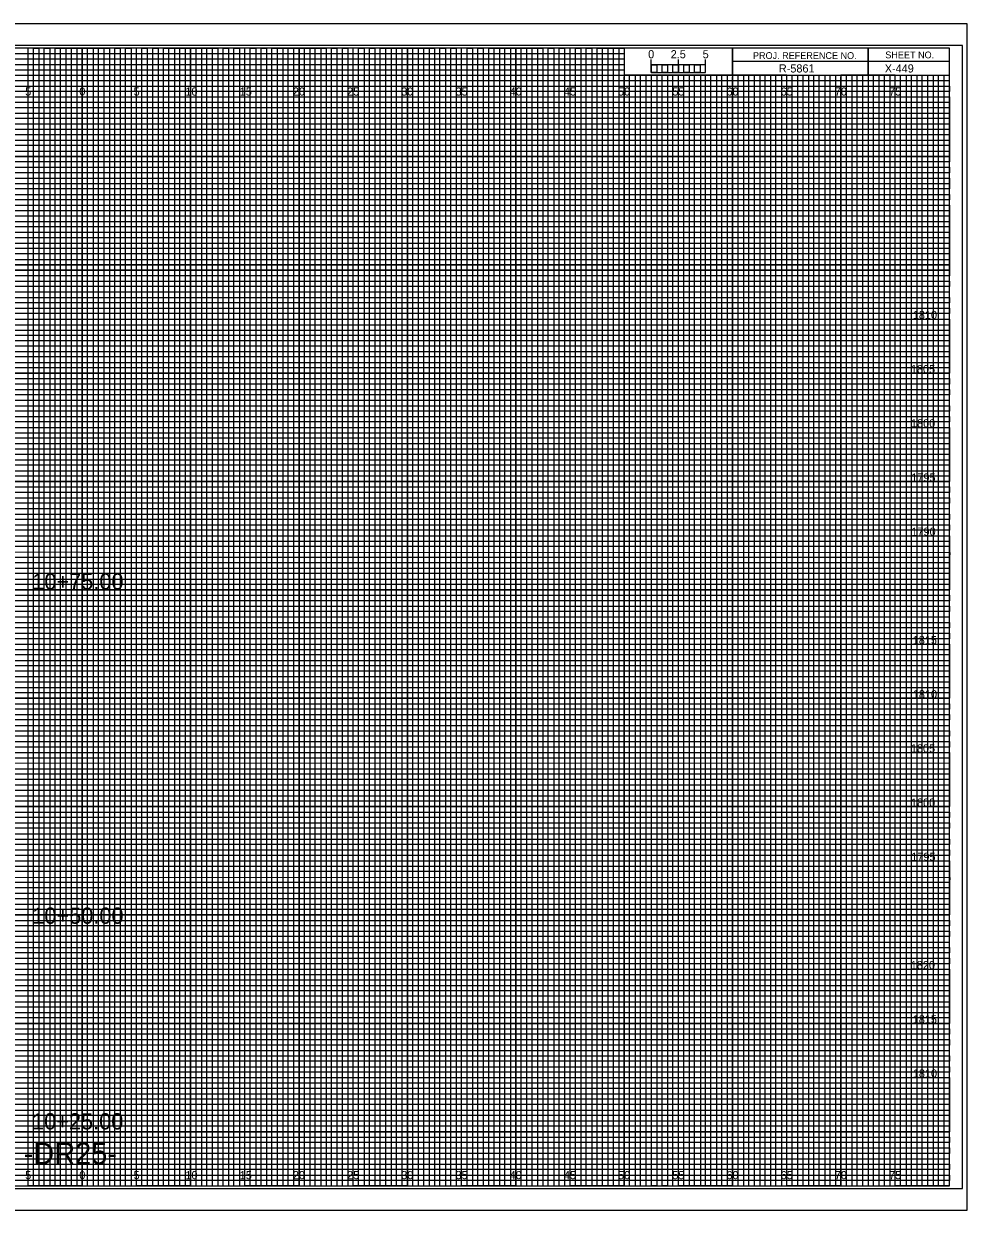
# Model space of a CAD drawing. Extents: x -7 to 162, y -2 to 327.
# Drawn here: x 74.6 to 161.7, y -2.3 to 107.3 of the extents above; entities that cross this region are included whole.
import ezdxf

# ---------------------------------------------------------------- set-up
doc = ezdxf.new("R2010")
doc.units = 0
for name, color, linetype in [('Prop Horizontal Alignment', 7, 'Continuous'), ('Prop XS Alignment Label', 7, 'Continuous'), ('Prop XS Bar Scale Labels', 7, 'Continuous'), ('Prop XS Project Number', 7, 'Continuous'), ('Prop XS Sheet Number', 7, 'Continuous'), ('Raster_Level_0', 7, 'Continuous'), ('Scratch_Level_3', 7, 'Continuous'), ('Sheet Cross Section CELL', 7, 'Continuous'), ('Sheet Cross Section Grid Major CELL', 7, 'Continuous'), ('Sheet Cross Section Grid Middle CELL', 7, 'Continuous'), ('Sheet Cross Section Grid Minor 1 CELL', 7, 'Continuous'), ('Sheet Cross Section Grid Minor 2 CELL', 7, 'Continuous'), ('Sheet Cross Section Scale CELL', 7, 'Continuous'), ('Sheet Cutting Line CELL', 7, 'Continuous'), ('Sheet DOT Grid CELL', 7, 'Continuous'), ('Sheet Plot Border Inside CELL', 7, 'Continuous'), ('Sheet Plot Border Outside CELL', 7, 'Continuous')]:
    doc.layers.add(name, color=color, linetype=linetype)

msp = doc.modelspace()

# ---------------------------------------------------------------- linework, layer by layer
at = {"layer": 'Sheet Cross Section CELL'}
for p, q in [((152.5, 105), (152.5, 102.5)), ((152.5, 102.5), (152.5, 105)), ((160, 103.75), (140, 103.75)), ((140, 103.75), (140, 102.5)), ((140, 102.5), (160, 102.5))]:
    msp.add_line(p, q, dxfattribs=at)
for points in [[(160, 105), (0, 105), (0, 0), (160, 0)], [(140, 105), (130, 105), (130, 102.52), (140, 102.52)], [(160, 105), (140, 105), (140, 102.5), (160, 102.5)]]:
    msp.add_lwpolyline(points, close=True, dxfattribs=at)
at = {"layer": 'Sheet Cross Section Grid Major CELL'}
for p, q in [((75, 105), (70, 105)), ((75, 0), (75, 105)), ((85, 105), (80, 105)), ((80, 105), (80, 0)), ((85, 0), (85, 105)), ((95, 105), (90, 105)), ((90, 105), (90, 0)), ((95, 0), (95, 105)), ((105, 105), (100, 105)), ((100, 105), (100, 0)), ((105, 0), (105, 105)), ((115, 105), (110, 105)), ((110, 105), (110, 0)), ((115, 0), (115, 105)), ((125, 105), (120, 105)), ((120, 105), (120, 0)), ((125, 0), (125, 105)), ((130, 105), (130, 0)), ((135, 0), (135, 102.5)), ((145, 102.5), (140, 102.5)), ((140, 102.5), (140, 0)), ((145, 0), (145, 102.5)), ((155, 102.5), (150, 102.5)), ((150, 102.5), (150, 0)), ((155, 0), (155, 102.5)), ((80, 0), (75, 0)), ((90, 0), (85, 0)), ((100, 0), (95, 0)), ((110, 0), (105, 0)), ((120, 0), (115, 0)), ((130, 0), (125, 0)), ((140, 0), (135, 0)), ((150, 0), (145, 0)), ((160, 0), (155, 0)), ((160, 0), (160, 0))]:
    msp.add_line(p, q, dxfattribs=at)
for points in [[(0, 100), (160, 100), (160, 95), (0, 95)], [(0, 90), (160, 90), (160, 85), (0, 85)], [(0, 80), (160, 80), (160, 75), (0, 75)], [(0, 70), (160, 70), (160, 65), (0, 65)], [(0, 60), (160, 60), (160, 55), (0, 55)], [(0, 50), (160, 50), (160, 45), (0, 45)], [(0, 40), (160, 40), (160, 35), (0, 35)], [(0, 30), (160, 30), (160, 25), (0, 25)], [(0, 20), (160, 20), (160, 15), (0, 15)], [(0, 10), (160, 10), (160, 5), (0, 5)]]:
    msp.add_lwpolyline(points, dxfattribs=at)
at = {"layer": 'Sheet Cross Section Grid Middle CELL'}
for points in [[(72.5, 0), (77.5, 0), (77.5, 105), (82.5, 105), (82.5, 0), (87.5, 0), (87.5, 105), (92.5, 105), (92.5, 0), (97.5, 0), (97.5, 105), (102.5, 105), (102.5, 0), (107.5, 0), (107.5, 105), (112.5, 105), (112.5, 0), (117.5, 0), (117.5, 105), (122.5, 105), (122.5, 0), (127.5, 0), (127.5, 105), (129.97, 105), (130, 105), (130, 102.5), (132.5, 102.5), (132.5, 0), (137.5, 0), (137.5, 102.5), (142.5, 102.5), (142.5, 0), (147.5, 0), (147.5, 102.5), (152.5, 102.5), (152.5, 0), (157.5, 0), (157.5, 102.5)], [(0, 102.5), (137.5, 102.5)], [(0, 92.5), (160, 92.5), (160, 97.5), (0, 97.5)], [(0, 82.5), (160, 82.5), (160, 87.5), (0, 87.5)], [(0, 72.5), (160, 72.5), (160, 77.5), (0, 77.5)], [(0, 62.5), (160, 62.5), (160, 67.5), (0, 67.5)], [(0, 52.5), (160, 52.5), (160, 57.5), (0, 57.5)], [(0, 42.5), (160, 42.5), (160, 47.5), (0, 47.5)], [(0, 32.5), (160, 32.5), (160, 37.5), (0, 37.5)], [(0, 22.5), (160, 22.5), (160, 27.5), (0, 27.5)], [(0, 12.5), (160, 12.5), (160, 17.5), (0, 17.5)], [(0, 2.5), (160, 2.5), (160, 7.5), (0, 7.5)]]:
    msp.add_lwpolyline(points, dxfattribs=at)
at = {"layer": 'Sheet Cross Section Grid Minor 1 CELL'}
for p, q in [((0, 104.5), (130, 104.5)), ((130, 104.5), (130, 103.99)), ((130, 103.99), (0, 103.99)), ((0, 103.5), (130, 103.5)), ((130, 102.95), (0, 102.95)), ((130, 103.5), (130, 102.95)), ((0, 102), (160, 102))]:
    msp.add_line(p, q, dxfattribs=at)
for points in [[(0, 101.5), (135, 101.5), (160, 101.5), (160, 101), (0, 101)], [(0, 100.5), (160, 100.5), (160, 99.5), (0, 99.5)], [(0, 99), (160, 99), (160, 98.5), (0, 98.49)], [(0, 98), (160, 98), (160, 97), (0, 97)], [(0, 96.5), (160, 96.5), (160, 96), (0, 96)], [(0, 95.5), (160, 95.5), (160, 94.5), (0, 94.5)], [(0, 94), (160, 94), (160, 93.5), (0, 93.5)], [(0, 93), (160, 93), (160, 92), (0, 92)], [(0, 91.5), (160, 91.5), (160, 91), (0, 91)], [(0, 90.5), (160, 90.5), (160, 89.5), (0, 89.5)], [(0, 89), (160, 89), (160, 88.5), (0, 88.5)], [(0, 88), (160, 88), (160, 86.98), (160, 86.5), (160, 86), (0, 86)], [(0, 87), (160, 87), (160, 86.5), (0, 86.5)], [(0, 85.5), (160, 85.5), (160, 84.5), (0, 84.52)], [(0, 84.52), (160, 84.5), (160, 84), (0, 84)], [(0, 83.5), (160, 83.5), (160, 83), (0, 83)], [(0, 82), (160, 82), (160, 81.5), (0, 81.5)], [(0, 81), (160, 81), (160, 80.5), (0, 80.5)], [(-0.04, 79.45), (160, 79.45), (160, 78.94), (-0.04, 78.94)], [(0, 78.5), (160, 78.5), (160, 78), (0, 78)], [(0, 77), (160, 77), (160, 76.5), (0, 76.5)], [(0, 76), (160, 76), (160, 75.5), (0, 75.5)], [(0, 74.5), (160, 74.5), (160, 74), (0, 74)], [(0, 73.5), (160, 73.5), (160, 73), (0, 73)], [(0, 72), (160, 72), (160, 71.5), (0, 71.5)], [(0, 71), (160, 71), (160, 70.5), (0, 70.5)], [(0, 69.5), (160, 69.5), (160, 68.99), (0, 69)], [(0, 68.5), (160, 68.5), (160, 68), (0, 68)], [(0, 67), (160, 67), (160, 66.5), (0, 66.5)], [(0, 66), (160, 66), (160, 65.5), (0, 65.5)], [(0, 64.5), (160, 64.5), (160, 64), (0, 64)], [(0, 63.5), (160, 63.5), (160, 63), (0, 63)], [(0, 62), (160, 62), (160, 61.5), (0, 61.5)], [(0, 61), (160, 61), (160, 60.5), (0, 60.5)], [(0, 59.5), (160, 59.5), (160, 59), (0, 59)], [(0, 58.5), (160.03, 58.45), (160, 58), (0, 58)], [(0, 57), (160, 57), (160, 56.5), (0, 56.5)], [(0, 56), (160, 56), (160, 55.5), (0, 55.5)], [(0, 54.5), (160, 54.5), (160, 54), (0, 54)], [(0, 53.5), (160, 53.5), (160, 53), (0, 53)], [(0, 52), (160, 52), (160, 51.5), (0, 51.5)], [(0, 51), (160, 51), (160, 50.5), (0, 50.5)], [(0, 49.5), (160, 49.5), (160, 49), (0, 49)], [(0, 48.5), (160, 48.5), (160, 48), (0, 48)], [(0, 47), (160, 47), (160, 46.5), (0, 46.5)], [(0, 46), (160, 46), (160, 45.5), (0, 45.5)], [(0, 44.5), (160, 44.5), (160, 44), (0, 44)], [(0, 43.5), (160, 43.5), (160, 43), (0, 43)], [(0, 42), (160, 42), (160, 41.5), (0, 41.5)], [(0, 41), (160, 41), (160, 40.5), (0, 40.5)], [(0, 39.5), (160, 39.5), (160, 38.99), (0, 39)], [(0, 38.5), (160, 38.5), (160, 38), (0, 38)], [(0, 37), (160, 37), (160, 36.5), (0, 36.5)], [(0, 36), (160, 36), (160, 35.5), (0, 35.5)], [(0, 34.5), (160, 34.5), (160, 34), (0, 34)], [(0, 33.5), (160, 33.5), (160, 33), (0, 33)], [(0, 32), (160, 32), (160, 31.5), (0, 31.5)], [(0, 31), (160, 31), (160, 30.5), (0, 30.5)], [(0, 29.5), (160, 29.5), (160, 29), (0, 29)], [(0, 28.5), (160.03, 28.46), (160, 28), (0, 28)], [(0, 27), (160, 27), (160, 26.5), (0, 26.5)], [(0, 26), (160, 26), (160, 25.5), (0, 25.5)], [(0, 24.5), (160, 24.5), (160, 24), (0, 24)], [(0, 23.5), (160, 23.5), (160, 23), (0, 23)], [(0, 22), (160, 22), (160, 21.5), (0, 21.5)], [(0, 21), (160, 21), (160, 20.5), (0, 20.5)], [(0, 19.5), (160, 19.5), (160, 19), (0, 19)], [(0, 18.5), (160, 18.5), (160, 18), (0, 18)], [(0, 17), (160, 17), (160, 16.5), (0, 16.5)], [(0, 16), (160, 16), (160, 15.5), (0, 15.5)], [(0, 14.5), (160, 14.5), (160, 14), (0, 14)], [(0, 13.5), (160, 13.5), (160, 13), (0, 13)], [(0, 12), (160, 12), (160, 11.5), (0, 11.5)], [(0, 11), (160, 11), (160, 10.5), (0, 10.5)], [(0, 9.5), (160, 9.5), (160, 9), (0, 9)], [(0, 8.5), (160, 8.5), (160, 8), (0, 8)], [(0, 7), (160, 7), (160, 6.5), (0, 6.5)], [(0, 6), (160, 6), (160, 5.5), (0, 5.5)], [(0, 4.5), (160, 4.5), (160, 4), (0, 4)], [(0, 3.5), (160, 3.5), (160, 3), (0, 3)], [(0, 2), (160, 2), (160, 1.5), (0, 1.5)], [(0, 1), (160, 1), (160, 0.5), (0, 0.5)]]:
    msp.add_lwpolyline(points, dxfattribs=at)
at = {"layer": 'Sheet Cross Section Grid Minor 2 CELL'}
for p, q in [((133.5, 102.5), (133, 102.5)), ((133, 102.5), (133, 0)), ((133.5, 0), (133.5, 102.5)), ((134.5, 102.5), (134, 102.5)), ((134, 102.5), (134, 0)), ((134.5, 0), (134.5, 102.5)), ((133, 0), (132.5, 0)), ((134, 0), (133.5, 0))]:
    msp.add_line(p, q, dxfattribs=at)
for points in [[(75, 0), (75.5, 0), (75.5, 105), (76, 105), (76, 0)], [(76, 0), (76.5, 0), (76.5, 105), (77, 105), (77, 0)], [(77.5, 0), (78, 0), (78, 105), (78.5, 105), (78.5, 0)], [(78.5, 0), (79, 0), (79, 105), (79.5, 105), (79.5, 0)], [(80, 0), (80.5, 0), (80.5, 105), (81, 105), (81, 0)], [(81, 0), (81.5, 0), (81.5, 105), (82, 105), (82, 0)], [(82.5, 0), (83, 0), (83, 105), (83.5, 105), (83.5, 0)], [(83.5, 0), (84, 0), (84, 105), (84.5, 105), (84.5, 0)], [(85, 0), (85.5, 0), (85.5, 105), (86, 105), (86, 0)], [(86, 0), (86.5, 0), (86.5, 105), (87, 105), (87, 0)], [(87.5, 0), (88, 0), (88, 105), (88.5, 105), (88.5, 0)], [(88.5, 0), (89, 0), (89, 105), (89.5, 105), (89.5, 0)], [(90, 0), (90.5, 0), (90.5, 105), (91, 105), (91, 0)], [(91, 0), (91.5, 0), (91.5, 105), (92, 105), (92, 0)], [(92.5, 0), (93, 0), (93, 105), (93.5, 105), (93.5, 0)], [(93.5, 0), (94, 0), (94, 105), (94.5, 105), (94.5, 0)], [(95, 0), (95.5, 0), (95.5, 105), (96, 105), (96, 0)], [(96, 0), (96.5, 0), (96.5, 105), (97, 105), (97, 0)], [(97.5, 0), (98, 0), (98, 105), (98.5, 105), (98.5, 0)], [(98.5, 0), (99, 0), (99, 105), (99.5, 105), (99.5, 0)], [(100, 0), (100.5, 0), (100.5, 105), (101, 105), (101, 0)], [(101, 0), (101.5, 0), (101.5, 105), (102, 105), (102, 0)], [(102.5, 0), (103, 0), (103, 105), (103.5, 105), (103.5, 0)], [(103.5, 0), (104, 0), (104, 105), (104.5, 105), (104.5, 0)], [(105, 0), (105.5, 0), (105.5, 105), (106, 105), (106, 0)], [(106, 0), (106.5, 0), (106.5, 105), (107, 105), (107, 0)], [(107.5, 0), (108, 0), (108, 105), (108.5, 105), (108.5, 0)], [(108.5, 0), (109, 0), (109, 105), (109.5, 105), (109.5, 0)], [(110, 0), (110.5, 0), (110.5, 105), (111, 105), (111, 0)], [(111, 0), (111.5, 0), (111.5, 105), (112, 105), (112, 0)], [(112.5, 0), (113, 0), (113, 105), (113.5, 105), (113.5, 0)], [(113.5, 0), (114, 0), (114, 105), (114.5, 105), (114.5, 0)], [(115, 0), (115.5, 0), (115.5, 105), (116, 105), (116, 0)], [(116, 0), (116.5, 0), (116.5, 105), (117, 105), (117, 0)], [(117.5, 0), (118, 0), (118, 105), (118.5, 105), (118.5, 0)], [(118.5, 0), (119, 0), (119, 105), (119.5, 105), (119.5, 0)], [(120, 0), (120.5, 0), (120.5, 105), (121, 105), (121, 0)], [(121, 0), (121.5, 0), (121.5, 105), (122, 105), (122, 0)], [(122.5, 0), (123, 0), (123, 105), (123.5, 105), (123.5, 0)], [(123.5, 0), (124, 0), (124, 105), (124.5, 105), (124.5, 0)], [(125, 0), (125.5, 0), (125.5, 105), (126, 105), (126, 0)], [(126, 0), (126.5, 0), (126.5, 105), (127, 105), (127, 0)], [(127.5, 0), (128, 0), (128, 105), (128.5, 105), (128.5, 0)], [(128.5, 0), (129, 0), (129, 105), (129.5, 105), (129.5, 0)], [(130, 0), (130.5, 0), (130.5, 102.5), (131.01, 102.5), (131.01, 0)], [(131, 0), (131.5, 0), (131.5, 102.5), (132, 102.5), (132, 0)], [(135, 0), (135.49, 0), (135.49, 102.5), (136, 102.5), (136, 0)], [(136, 0), (136.5, 0), (136.5, 102.5), (137.03, 102.5), (137.03, 0)], [(137.5, 0), (138, 0), (138, 102.5), (138.5, 102.5), (138.5, 0)], [(138.5, 0), (139, 0), (139, 102.5), (139.5, 102.5), (139.5, 0)], [(140, 0), (140.5, 0), (140.5, 102.5), (141, 102.5), (141, 0)], [(141, 0), (141.5, 0), (141.5, 102.5), (142, 102.5), (142, 0)], [(142.5, 0), (143, 0), (143, 102.5), (143.5, 102.5), (143.5, 0)], [(143.5, 0), (144, 0), (144, 102.5), (144.5, 102.5), (144.5, 0)], [(145, 0), (145.5, 0), (145.5, 102.5), (146, 102.5), (146, 0)], [(146, 0), (146.5, 0), (146.5, 102.5), (147, 102.5), (147, 0)], [(147.5, 0), (148, 0), (148, 102.5), (148.5, 102.5), (148.5, 0)], [(148.5, 0), (149, 0), (149, 102.5), (149.5, 102.5), (149.5, 0)], [(150, 0), (150.5, 0), (150.5, 102.5), (151, 102.5), (151, 0)], [(151, 0), (151.5, 0), (151.5, 102.5), (152, 102.5), (152, 0)], [(152.5, 0), (153, 0), (153, 102.5), (153.5, 102.5), (153.5, 0)], [(153.5, 0), (154, 0), (154, 102.5), (154.5, 102.5), (154.5, 0)], [(155, 0), (155.5, 0), (155.5, 102.5), (156, 102.5), (156, 0)], [(156, 0), (156.5, 0), (156.5, 102.5), (157, 102.5), (157, 0)], [(157.5, 0), (158, 0), (158, 102.5), (158.5, 102.5), (158.5, 0)], [(158.5, 0), (159, 0), (159, 102.5), (159.5, 102.5), (159.5, 0)]]:
    msp.add_lwpolyline(points, dxfattribs=at)
at = {"layer": 'Sheet Cross Section Scale CELL'}
for p, q in [((132.5, 102.75), (132.5, 103.95)), ((132.5, 103.45), (132.5, 103.95)), ((135, 102.75), (135, 103.95)), ((137.5, 102.75), (137.5, 103.95)), ((137.5, 103.45), (137.5, 103.95))]:
    msp.add_line(p, q, dxfattribs=at)
for points in [[(137.5, 103.45), (132.5, 103.45), (132.5, 102.75), (137.5, 102.75)], [(132.5, 103.45), (133, 103.45), (133, 102.75), (132.5, 102.75)], [(133.5, 103.45), (134, 103.45), (134, 102.75), (133.5, 102.75)], [(134.5, 103.45), (135, 103.45), (135, 102.75), (134.5, 102.75)], [(135.5, 103.45), (136, 103.45), (136, 102.75), (135.5, 102.75)], [(136.5, 103.45), (137, 103.45), (137, 102.75), (136.5, 102.75)]]:
    msp.add_lwpolyline(points, close=True, dxfattribs=at)
at = {"layer": 'Sheet Cutting Line CELL'}
for p, q in [((161.65, 107.25), (-6.7, 107.25)), ((-6.7, -2.25), (161.65, -2.25))]:
    msp.add_line(p, q, dxfattribs=at)
at = {"layer": 'Sheet DOT Grid CELL'}
for p, q in [((75, 0), (75, 105)), ((80, 0), (80, 105)), ((85, 0), (85, 105)), ((90, 0), (90, 105)), ((95, 0), (95, 105)), ((100, 0), (100, 105)), ((105, 0), (105, 105)), ((110, 0), (110, 105)), ((115, 0), (115, 105)), ((120, 0), (120, 105)), ((125, 0), (125, 105)), ((130, 0), (130, 102.34)), ((135, 0), (135, 102.34)), ((140, 0), (140, 102.34)), ((145, 0), (145, 102.34)), ((150, 0), (150, 102.34)), ((155, 0), (155, 102.34)), ((0, 100), (160, 100)), ((0, 95), (160, 95)), ((0, 90), (160, 90)), ((0, 85), (160, 85)), ((0, 80), (160, 80)), ((0, 75), (160, 75)), ((0, 70), (160, 70)), ((0, 65), (160, 65)), ((0, 60), (160, 60)), ((0, 55), (160, 55)), ((0, 50), (160, 50)), ((0, 45), (160, 45)), ((0, 40), (160, 40)), ((0, 35), (160, 35)), ((0, 30), (160, 30)), ((0, 25), (160, 25)), ((0, 20), (160, 20)), ((0, 15), (160, 15)), ((0, 10), (160, 10)), ((0, 5), (160, 5))]:
    msp.add_line(p, q, dxfattribs=at)
at = {"layer": 'Sheet Plot Border Inside CELL'}
msp.add_lwpolyline([(-5.4, -0.25), (161.2, -0.25), (161.2, 105.25), (-5.4, 105.25)], close=True, dxfattribs=at)
at = {"layer": 'Sheet Plot Border Outside CELL'}
msp.add_lwpolyline([(-6.7, -2.25), (161.65, -2.25), (161.65, 107.25), (-6.7, 107.25)], close=True, dxfattribs=at)

# ---------------------------------------------------------------- texts
at = {"layer": 'Prop Horizontal Alignment'}
for s, p in [('10+75.00', (75.39, 55.03)), ('10+50.00', (75.39, 24.19)), ('10+25.00', (75.37, 5.21))]:
    msp.add_text(s, height=1.5, dxfattribs=at).set_placement(p)
at = {"layer": 'Prop XS Alignment Label'}
msp.add_text('-DR25-', height=2, dxfattribs=at).set_placement((74.59, 2))
at = {"layer": 'Prop XS Bar Scale Labels'}
for s, p in [('2.5', (134.29, 104.06)), ('5', (137.24, 104.06))]:
    msp.add_text(s, height=0.75, dxfattribs=at).set_placement(p)
at = {"layer": 'Prop XS Project Number'}
msp.add_text('R-5861', height=0.75, dxfattribs=at).set_placement((144.27, 102.75))
at = {"layer": 'Prop XS Sheet Number'}
msp.add_text('X-449', height=0.75, dxfattribs=at).set_placement((154.04, 102.75))
at = {"layer": 'Raster_Level_0'}
for s, p in [('5', (74.74, 100.62)), ('0', (79.73, 100.62)), ('0', (79.73, 100.62)), ('5', (84.74, 100.62)), ('10', (89.52, 100.62)), ('15', (94.53, 100.62)), ('20', (99.43, 100.62)), ('25', (104.44, 100.62)), ('30', (109.43, 100.62)), ('35', (114.44, 100.62)), ('40', (119.43, 100.62)), ('45', (124.44, 100.62)), ('50', (129.43, 100.62)), ('55', (134.44, 100.62)), ('60', (139.43, 100.62)), ('65', (144.44, 100.62)), ('70', (149.43, 100.62)), ('75', (154.44, 100.62)), ('5', (74.74, 0.62)), ('0', (79.73, 0.62)), ('0', (79.73, 0.62)), ('5', (84.74, 0.62)), ('10', (89.52, 0.62)), ('15', (94.53, 0.62)), ('20', (99.43, 0.62)), ('25', (104.44, 0.62)), ('30', (109.43, 0.62)), ('35', (114.44, 0.62)), ('40', (119.43, 0.62)), ('45', (124.44, 0.62)), ('50', (129.43, 0.62)), ('55', (134.44, 0.62)), ('60', (139.43, 0.62)), ('65', (144.44, 0.62)), ('70', (149.43, 0.62)), ('75', (154.44, 0.62))]:
    msp.add_text(s, height=0.75, dxfattribs=at).set_placement(p)
at = {"layer": 'Scratch_Level_3'}
for s, p in [('1810', (156.63, 80)), ('1805', (156.45, 75)), ('1800', (156.46, 70)), ('1795', (156.49, 65)), ('1790', (156.5, 60)), ('1815', (156.62, 50)), ('1810', (156.63, 45)), ('1805', (156.45, 40)), ('1800', (156.46, 35)), ('1795', (156.49, 30)), ('1820', (156.44, 20)), ('1815', (156.62, 15)), ('1810', (156.63, 10))]:
    msp.add_text(s, height=0.75, dxfattribs=at).set_placement(p)
at = {"layer": 'Sheet Cross Section CELL'}
for s, p in [('PROJ. REFERENCE NO.', (141.88, 104)), ('SHEET NO.', (154.09, 104.06))]:
    msp.add_text(s, height=0.625, dxfattribs=at).set_placement(p)
at = {"layer": 'Sheet Cross Section Scale CELL'}
msp.add_text('0', height=0.75, dxfattribs=at).set_placement((132.21, 104.06))

doc.saveas('drawing.dxf')
